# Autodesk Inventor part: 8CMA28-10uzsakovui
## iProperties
Created: 2009-10
Part Number: 8CMA28-10uzsakovui
Document SubType Name: Modeling
Designer: Darius
Author: Darius
Translation Standard: STEP AP203
File Name: 8CMA28-10.STEP
Preprocessor: SolidWorks 2003240
Postprocessor: Build: 272, Release: 10 SP3a - Date: Thu 12/15/2005
Sent Units: MILLIMETERS
Uncertainty: 1e-05
